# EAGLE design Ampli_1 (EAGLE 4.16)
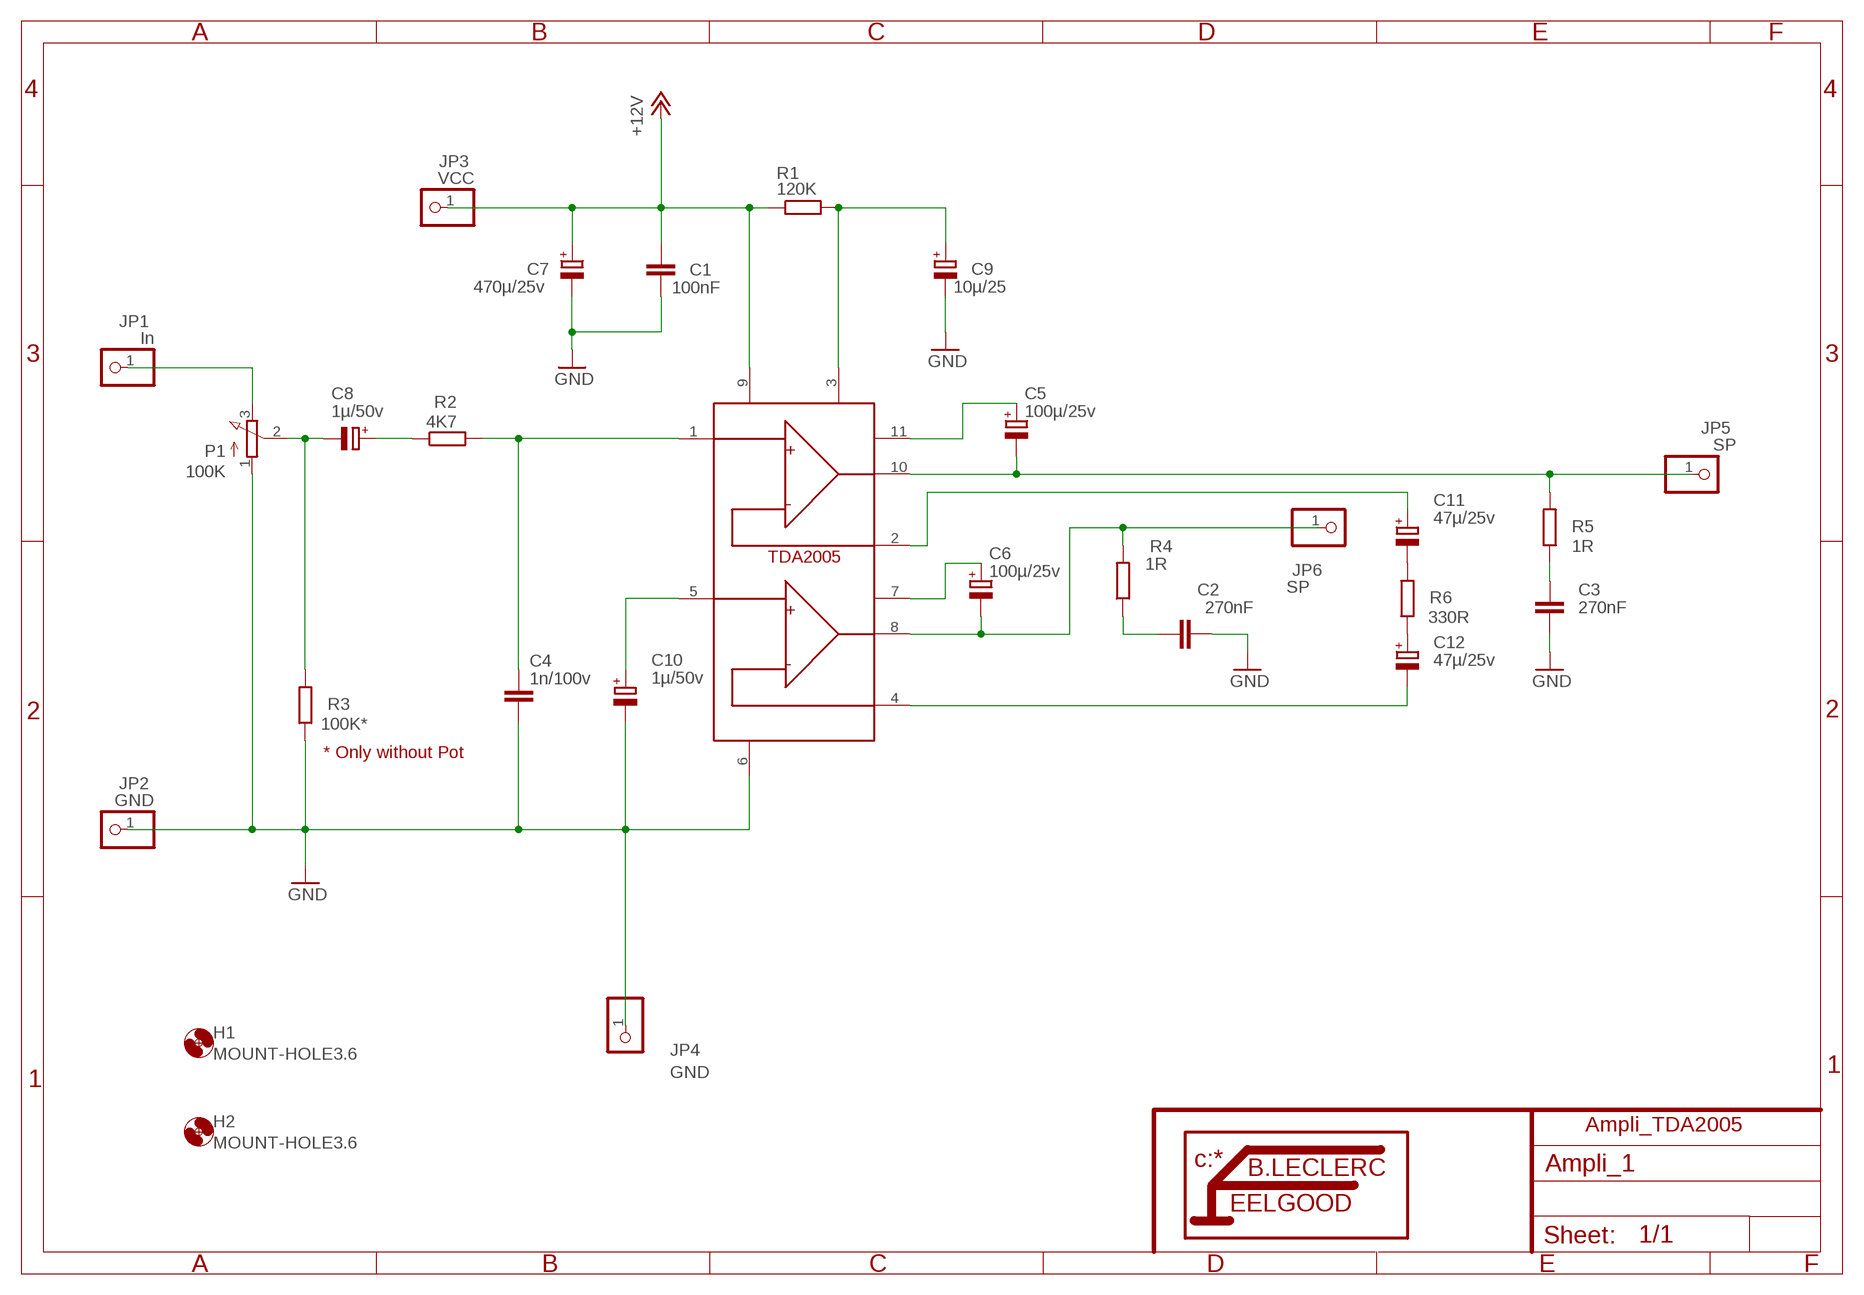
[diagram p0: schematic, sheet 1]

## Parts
C1  100nF  C-EU102-043X133  [C102-043X133]
C2  270nF  C-EU102-043X133  [C102-043X133]
C3  270nF  C-EU102-043X133  [C102-043X133]
C4  1n/100v  C-EU025_050-025X075  [C025_050-025X075]
C5  100µ/25v  CPOL-EUE3.5-10  [E3,5-10]
C6  100µ/25v  CPOL-EUE3.5-10  [E3,5-10]
C7  470µ/25v  CPOL-EUE5-13  [E5-13]
C8  1µ/50v  CPOL-EUE2,5-6E  [E2,5-6E]
C9  10µ/25  CPOL-EUE2,5-6E  [E2,5-6E]
C10  1µ/50v  CPOL-EUE2,5-6E  [E2,5-6E]
C11  47µ/25v  CPOL-EUE2,5-6E  [E2,5-6E]
C12  47µ/25v  CPOL-EUE2,5-6E  [E2,5-6E]
H1  MOUNT-HOLE3.6  [3,6]
H2  MOUNT-HOLE3.6  [3,6]
JP1  In  PINHD-1X1  [1X01]
JP2  GND  PINHD-1X1  [1X01]
JP3  VCC  PINHD-1X1  [1X01]
JP4  GND  PINHD-1X1  [1X01]
JP5  SP  PINHD-1X1  [1X01]
JP6  SP  PINHD-1X1  [1X01]
P1  100K  STD-EU  [STD-EU]
R1  120K  R-EU_0207/10  [0207/10]
R2  4K7  R-EU_0207/10  [0207/10]
R3  100K*  R-EU_0207/10  [0207/10]
R4  1R  R-EU_0207/12  [0207/12]
R5  1R  R-EU_0207/12  [0207/12]
R6  330R  R-EU_0207/10  [0207/10]
U$2  TDA2005  [MULTIWATT-11]

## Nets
+12V: C1.1 C7.+ JP3.1 R1.1 U$2.9
GND: C1.2 C2.2 C3.2 C4.2 C7.- C9.- C10.- JP2.1 JP4.1 P1.1(A) R3.1 U$2.6
N$1: C11.- R6.2
N$2: C12.+ R6.1
N$3: C4.1 R2.2 U$2.1
N$4: C9.+ R1.2 U$2.3
N$5: C8.+ R2.1
N$6: C8.- P1.2(S) R3.2
N$7: JP1.1 P1.3(E)
N$8: C12.- U$2.4
N$9: C10.+ U$2.5
N$10: C6.- JP6.1 R4.2 U$2.8
N$11: C6.+ U$2.7
N$12: C5.- JP5.1 R5.2 U$2.10
N$13: C5.+ U$2.11
N$14: C2.1 R4.1
N$15: C11.+ U$2.2
N$16: C3.1 R5.1

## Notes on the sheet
- * Only without Pot
- Ampli_TDA2005

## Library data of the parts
C1-C4 = rcl:C-EU: CAPACITOR, European symbol
C5-C12 = rcl:CPOL-EU: POLARIZED CAPACITOR, European symbol
H1 H2 = holes:MOUNT-HOLE: MOUNTING HOLE with drill center marker
JP1-JP6 = pinhead:PINHD-1X1: PIN HEADER
P1 = pot:STD-EU
R1-R6 = rcl:R-EU_: RESISTOR, European symbol
U$2 = st-microelectronics:TDA2005

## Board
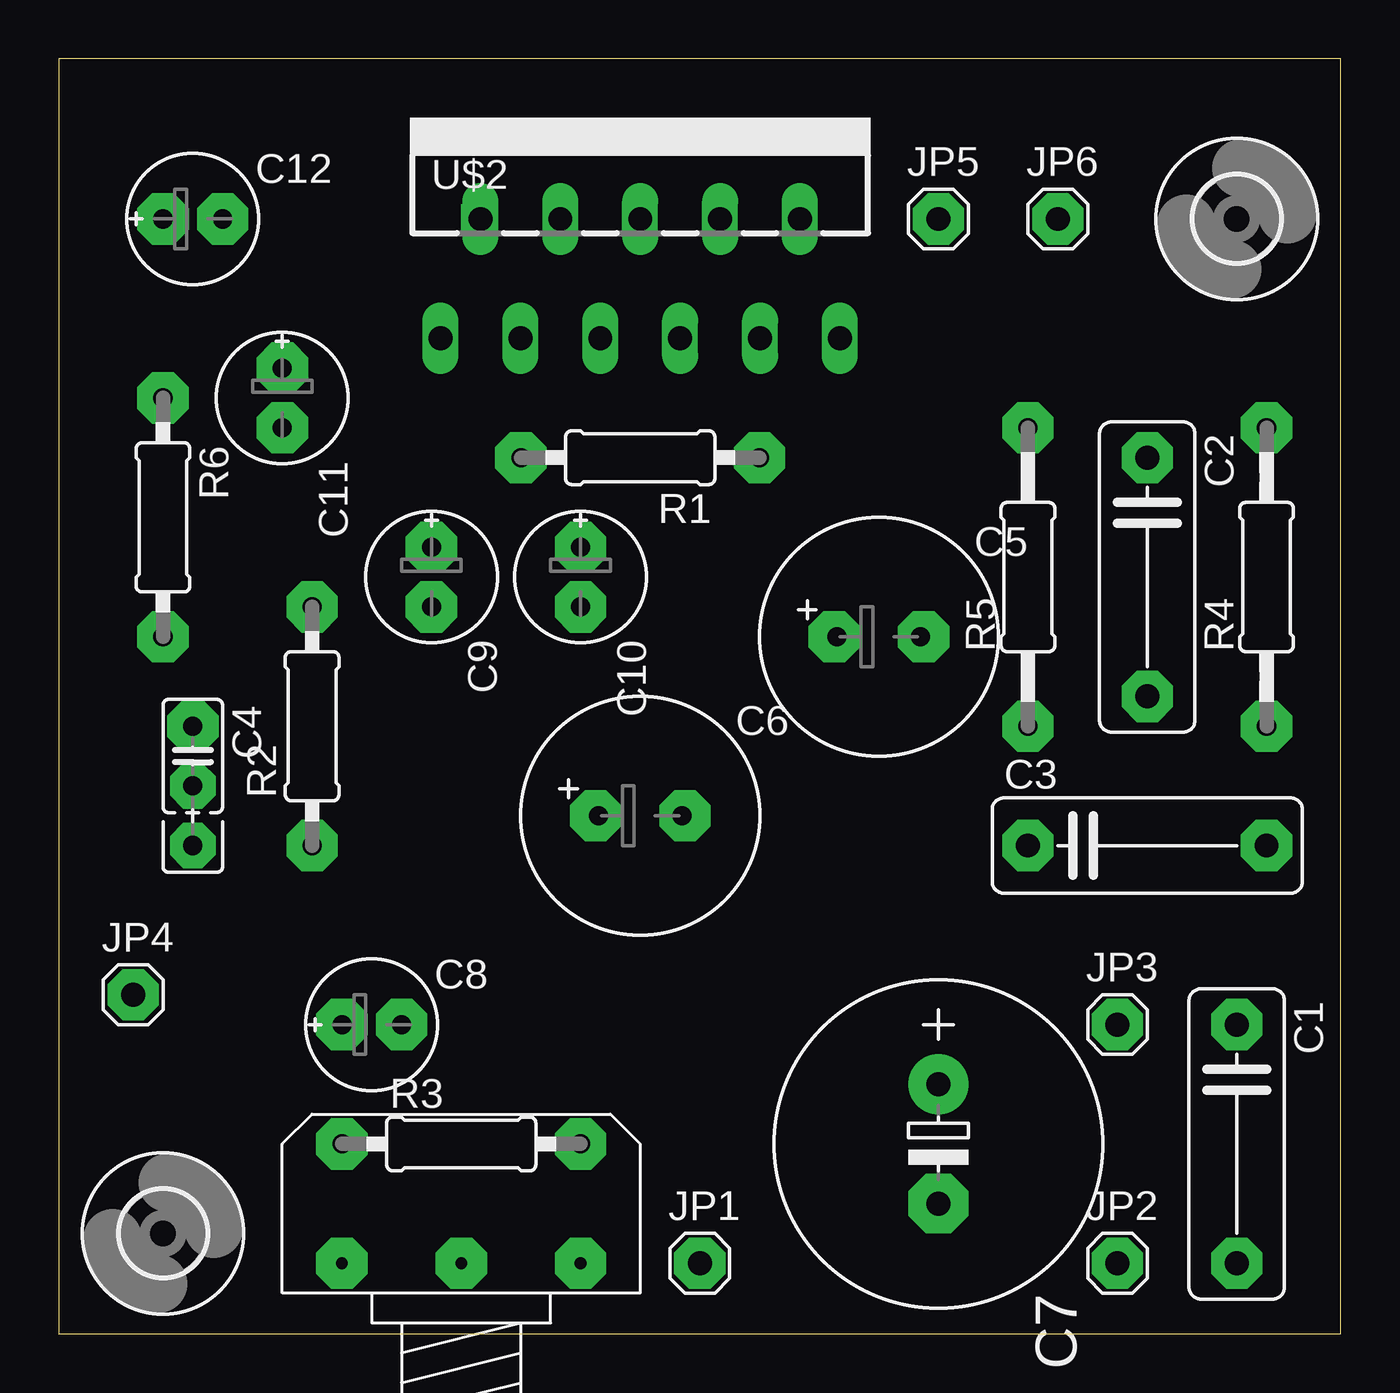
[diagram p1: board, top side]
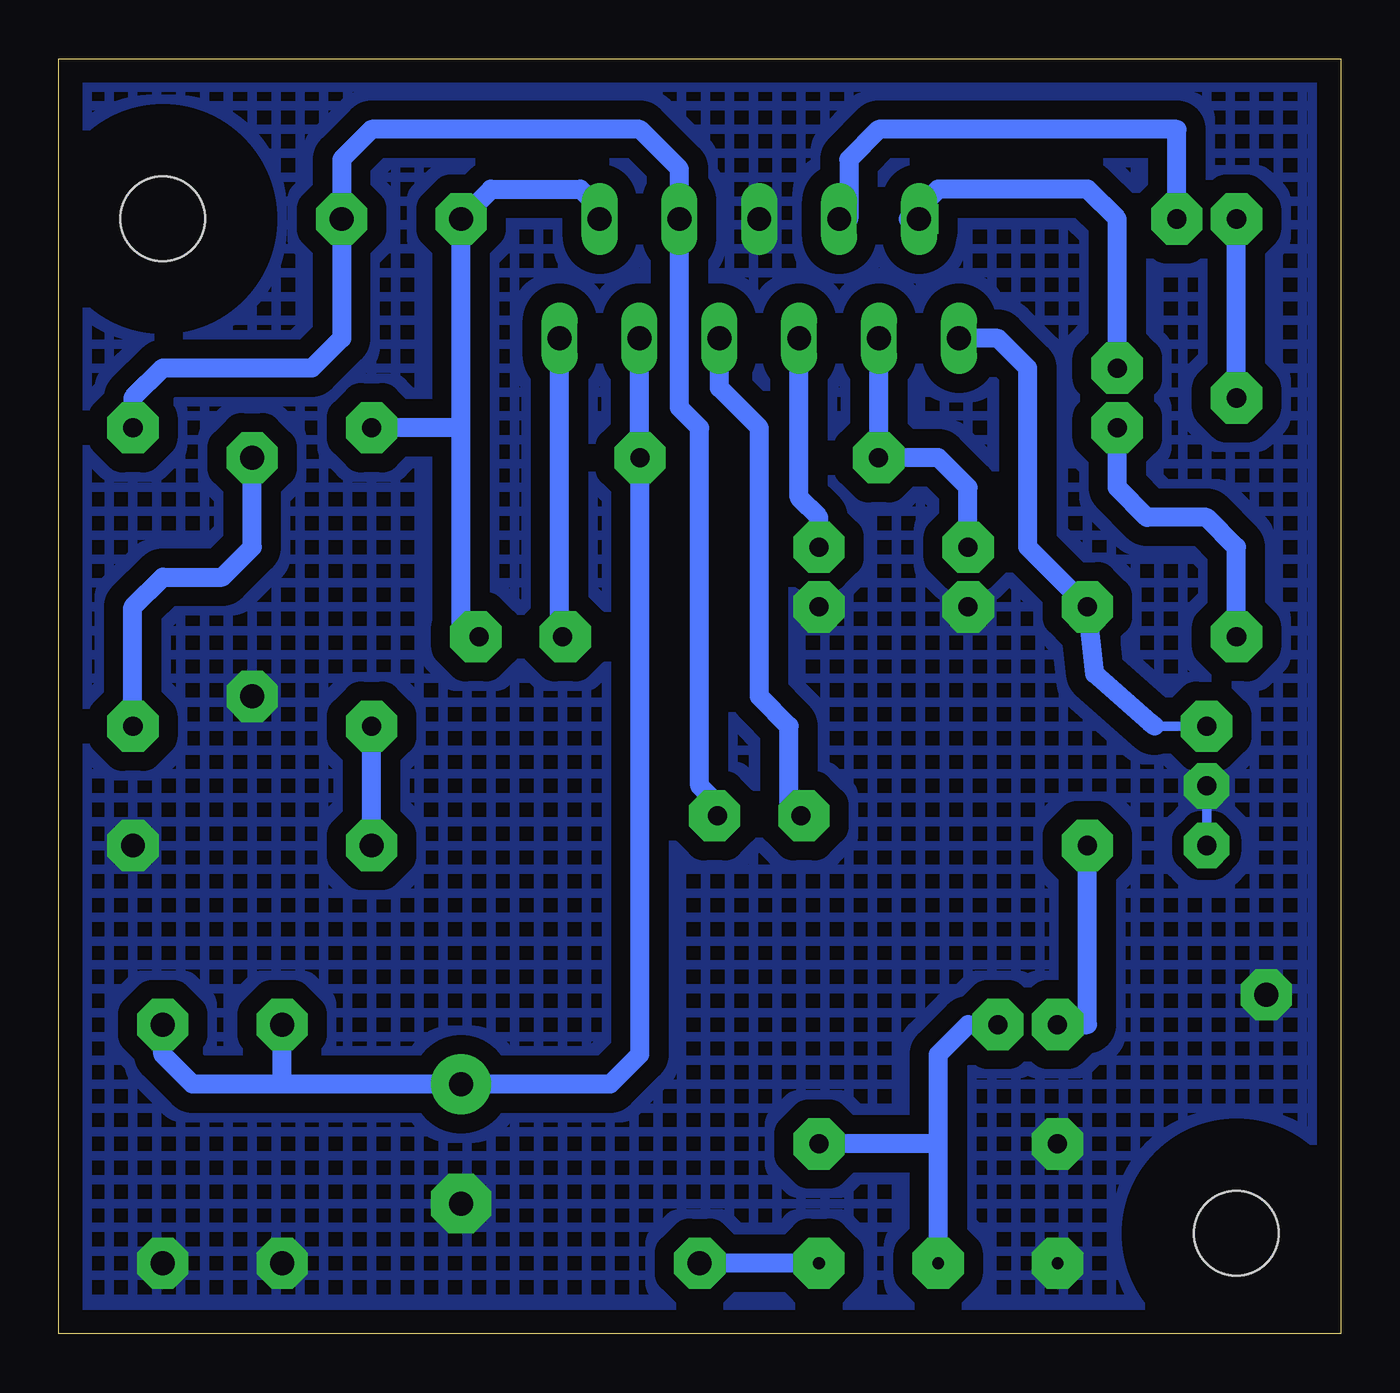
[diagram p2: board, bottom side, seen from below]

Size 54.59 x 54.28 mm. Coordinates in mm from the lower left corner, seen from the top.
Outline: 0,0 54.59,0 54.59,54.28 0,54.28 0,0
Copper layers (1*16): Top 0.035mm / dielectric 1.5mm / Bottom 0.035mm
Design rules "default": minimum track width 10mil, minimum drill 24mil, track to track 8mil, track to pad 8mil, pad to pad 8mil, via to via 8mil, smd to smd 8mil, copper to edge 40mil, drill to drill 8mil, minimum pad ring 10mil, minimum via ring 8mil, stop-mask expansion 4mil, vias tented up to drill 0mil, thermal gap 10mil

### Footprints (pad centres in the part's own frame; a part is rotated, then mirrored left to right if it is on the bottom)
C102-043X133 = drill 1.016 octagon: 1 -5.08,0; 2 5.08,0
C025_050-025X075 = drill 0.813 octagon: 1 -1.27,0; 2 1.27,0; 3 3.81,0
E3,5-10 = drill 0.813 pad 1.6 round: + -1.778,0 | drill 0.813 pad 1.6 octagon: - 1.778,0
E5-13 = drill 1.016 pad 2.54 round: + -2.54,0 | drill 1.016 pad 2.54 octagon: - 2.54,0
E2,5-6E = drill 0.813 pad 1.575 round: + -1.27,0 | drill 0.813 pad 1.575 octagon: - 1.27,0
3,6 = hole 3.6: 0,0
1X01 = drill 1.016 octagon: 1 0,0
STD-EU = drill 0.5 pad 2.184 octagon: 1 -5.08,0; 2 0,0; 3 5.08,0
0207/10 = drill 0.813 octagon: 1 -5.08,0; 2 5.08,0
0207/12 = drill 0.813 octagon: 1 -6.35,0; 2 6.35,0
MULTIWATT-11 = drill 1.016 long: 1 -8.5,-6.35; 2 -6.8,-1.27; 3 -5.1,-6.35; 4 -3.4,-1.27; 5 -1.7,-6.35; 6 0,-1.27; 7 1.7,-6.35; 8 3.4,-1.27; 9 5.1,-6.35; 10 6.8,-1.27; 11 8.5,-6.35

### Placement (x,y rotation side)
C1  50.16,8.09 270 top
C2  46.35,32.22 270 top
C3  46.35,20.79 0 top
C4  5.71,24.6 270 top
C5  34.92,29.68 0 top
C6  24.76,22.06 0 top
C7  37.46,8.09 270 top
C8  13.33,13.17 0 top
C9  15.87,32.22 270 top
C10  22.22,32.22 270 top
C11  9.52,39.84 270 top
C12  5.71,47.46 0 top
H1  50.16,47.46 0 top
H2  4.44,4.28 0 top
JP1  27.3,3.01 0 top
JP2  45.08,3.01 0 top
JP3  45.08,13.17 0 top
JP4  3.17,14.44 0 top
JP5  37.46,47.46 0 top
JP6  42.54,47.46 0 top
P1  17.14,3.01 0 top
R1  24.76,37.3 180 top
R2  10.79,25.87 90 top
R3  17.14,8.09 0 top
R4  51.43,32.22 90 top
R5  41.27,32.22 90 top
R6  4.44,34.76 270 top
U$2  24.76,48.73 0 top

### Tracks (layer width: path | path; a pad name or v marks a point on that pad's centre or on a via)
+12V
  Bottom 0.813: U$2.9 29.86,37.32 R1.1 29.84,11.9 31.11,10.63 C7.+ 45.08,10.63 | 45.08,10.63 48.89,10.63 50.16,11.9 C1.1 | 45.08,10.63 JP3.1
GND  (via drill 0.5 pad 1.27, 0.5 pad 2.18, 0.6 pad 1.93)
  Bottom 0.406: v5.71,20.79 C4.2
  other vias: 3.17,14.44 12.06,8.09 15.87,30.95 22.22,30.95 46.35,27.14 51.43,20.79 50.16,3.01 45.08,3.01 24.76,47.46 5.71,23.33
  pour Bottom (isolate 0.813, no thermals, hatched): 0.63,53.81 53.97,53.81 53.97,52.54 53.97,0.47 0.63,0.47
N$1
  Bottom 0.813: R6.2 4.44,33.49 5.71,34.76 8.25,34.76 9.52,36.03 C11.-
N$2
  Bottom 0.813: R6.1 C12.+
N$3
  Bottom 0.406: 8.11,26.03 8.25,26.03 8.25,25.87 C4.1
  Bottom 0.813: U$2.1 14.6,42.38 13.33,41.11 13.33,33.49 R2.2 10.47,28.09 8.11,26.03 7.93,25.87
N$4
  Bottom 0.813: U$2.3 19.66,37.32 R1.2 17.14,37.3 15.87,36.03 C9.+
N$5
  Bottom 0.813: R2.1 10.79,13.17 C8.+
N$6
  Bottom 0.813: P1.2 17.14,8.09 | 17.14,8.09 17.14,11.9 15.87,13.17 C8.- | 17.14,8.09 R3.2
N$7
  Bottom 0.813: P1.3 JP1.1
N$8
  Bottom 0.813: U$2.4 20.95,47.46 20.95,50 19.68,51.27 6.98,51.27 C12.-
N$9
  Bottom 0.813: U$2.5 23.06,35.6 22.22,34.76 C10.+
N$10
  Bottom 0.813: C6.- 26.03,22.06 27.3,23.33 27.3,38.57 28.16,39.43 U$2.8 28.16,49.59 29.84,51.27 41.27,51.27 42.54,50 JP6.1 42.54,42.38 43.81,41.11 50.16,41.11 51.43,39.84 R4.2
N$11
  Bottom 0.813: U$2.7 26.46,40.27 24.76,38.57 24.76,27.14 23.49,25.87 23.49,22.06 C6.+
N$12
  Bottom 0.813: U$2.10 31.56,47.91 32.38,48.73 36.19,48.73 JP5.1 37.46,38.57 | 37.46,38.57 R5.2 | 37.46,38.57 37.46,29.68 C5.- 36.19,29.68
N$13
  Bottom 0.813: C5.+ 33.65,29.68 33.26,30.07 U$2.11
N$14
  Bottom 0.813: C2.1 46.35,33.49 47.62,32.22 50.16,32.22 51.43,30.95 R4.1
N$15
  Bottom 0.813: C11.+ 9.52,47.46 10.79,48.73 17.14,48.73 18.41,47.46 U$2.2
N$16
  Bottom 0.813: C3.1 R5.1
N$17  (via drill 0.5 pad 2.18)
  other vias: 4.44,39.84
N$18  (via drill 0.5 pad 2.18)
  other vias: 4.44,29.68
N$19  (via drill 0.5 pad 2.18)
  other vias: 4.44,47.46
N$20  (via drill 0.5 pad 2.18)
  other vias: 6.98,47.46
N$21  (via drill 0.5 pad 2.18)
  other vias: 9.52,41.11
N$22  (via drill 0.5 pad 2.18)
  other vias: 9.52,38.57
N$23  (via drill 0.5 pad 2.18)
  other vias: 5.71,25.87
N$24  (via drill 0.5 pad 1.27)
  other vias: 21.27,47.46
N$25  (via drill 0.5 pad 2.18)
  other vias: 10.79,30.95
N$26  (via drill 0.5 pad 2.18)
  other vias: 10.79,20.79
N$27  (via drill 0.5 pad 2.18)
  other vias: 12.06,13.17
N$28  (via drill 0.5 pad 2.18)
  other vias: 14.6,13.17
N$29  (via drill 0.5 pad 1.27)
  other vias: 28.25,47.46
N$30  (via drill 0.5 pad 2.18)
  other vias: 22.22,33.49
N$31  (via drill 0.5 pad 2.18)
  other vias: 19.68,37.3
N$32  (via drill 0.5 pad 2.18)
  other vias: 29.84,37.3
N$33  (via drill 0.5 pad 2.18)
  other vias: 15.87,33.49
N$34  (via drill 0.5 pad 1.27)
  other vias: 26.35,42.38
N$35  (via drill 0.5 pad 2.18)
  other vias: 41.27,38.57
N$36  (via drill 0.5 pad 2.18)
  other vias: 41.27,25.87
N$37  (via drill 0.5 pad 2.18)
  other vias: 41.27,20.79
N$38  (via drill 0.5 pad 1.27)
  other vias: 16.19,42.38
N$39  (via drill 0.5 pad 1.27)
  other vias: 23.17,42.38
N$40  (via drill 0.5 pad 2.18)
  other vias: 50.16,13.17
N$41  (via drill 0.5 pad 2.18)
  other vias: 51.43,38.57
N$42  (via drill 0.5 pad 2.18)
  other vias: 51.43,25.87
N$43  (via drill 0.5 pad 2.18)
  other vias: 46.35,37.3
N$44  (via drill 0.5 pad 1.27)
  other vias: 29.84,42.38
N$45  (via drill 0.5 pad 2.18)
  other vias: 33.02,29.68
N$46  (via drill 0.5 pad 2.18)
  other vias: 36.83,29.68
N$47  (via drill 0.5 pad 2.18)
  other vias: 27.3,3.01
N$48  (via drill 0.5 pad 1.27)
  other vias: 31.43,47.46
N$49  (via drill 0.5 pad 2.18)
  other vias: 37.46,47.46
N$50  (via drill 0.5 pad 2.18)
  other vias: 42.54,47.46
N$51  (via drill 0.5 pad 2.18)
  other vias: 45.08,13.17
N$53  (via drill 0.5 pad 2.18)
  other vias: 22.86,22.06
N$54  (via drill 0.5 pad 2.18)
  other vias: 26.66,22.06
N$55  (via drill 0.5 pad 1.27)
  other vias: 17.77,47.46
N$56  (via drill 0.5 pad 2.18)
  other vias: 22.22,8.09
N$57  (via drill 0.5 pad 1.27)
  other vias: 19.68,42.38
N$58  (via drill 0.5 pad 1.27)
  other vias: 33.33,42.38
